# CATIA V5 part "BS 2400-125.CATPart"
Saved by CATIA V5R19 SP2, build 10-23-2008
Part number: BS 2400-125
Bounding box of the stored display mesh (mm): x -37.351 to 37.351, y -37.351 to 37.351, z 0 to 295
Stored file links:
  C:\Users\Bora\Desktop\3D Katı model\BS serisi\BS 2400\BS 2400-125.CATPart
  C:\Program Files\Dassault Systemes\B19\intel_a\reffiles\standard\MetricThickPitch.txt
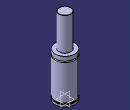
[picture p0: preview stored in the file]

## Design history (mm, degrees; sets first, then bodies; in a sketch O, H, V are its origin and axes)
Body1 (main body)
  Sketch1 on yz-plane, origin (0, 0, 0), H (0, 1, 0), V (0, 0, 1)
    point P1 (22.5, 294)
    point P3 (22.5, 294)
    point P7 (37.5, 153.5)
    point P9 (37.5, 153.5)
    point P10 (37.5, 148.5)
    point P14 (37.5, 148.5)
    line L1 (22.5, 294) -> (22.5, 169)
    arc A1 centre (21.5, 294) radius 1 from (22.5, 294) to (21.5, 295) ccw
    line L2 (37.5, 0) -> (37.5, 8)
    line L3 (37.5, 153.5) -> (37.5, 169)
    arc A2 centre (37.5, 151) radius 2.5 from (37.5, 153.5) to (37.5, 148.5) ccw
    line L4 (34.5, 13) -> (34.5, 8)
    line L5 (37.5, 13) -> (37.5, 148.5)
    line L6 (21.5, 295) -> (0, 295)
    point P15 (0, 295)
    line L7 (22.5, 169) -> (37.5, 169)
    line L8 (0, 0) -> (37.5, 0)
    line L9 (34.5, 13) -> (37.5, 13)
    line L10 (34.5, 8) -> (37.5, 8)
    coincidence: P15 V, P1 P3, P7 P9, P10 P14
    tangency: L6 A1
    horizontal: L7 H, L8 H, L9 H, L10 H
  Shaft1: profile Sketch1, axis Sketch1.V, angle 360
  Sketch2 on face of Shaft1 from Sketch1.L8, origin (0, 0, 0), H (1, 0, 0), V (0, -1, 0)
    point P1 (20, 0)
    distance P1 V = 20
  Hole1: placed by Sketch2, at (20, 0, 0) direction (0, 0, 1), diameter 6.647, depth 5, threaded "M8", thread diameter 8, thread depth 5, pitch 1.25
  CircPattern1: of Hole1, instances 4, angular step 90, axis from xy-plane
